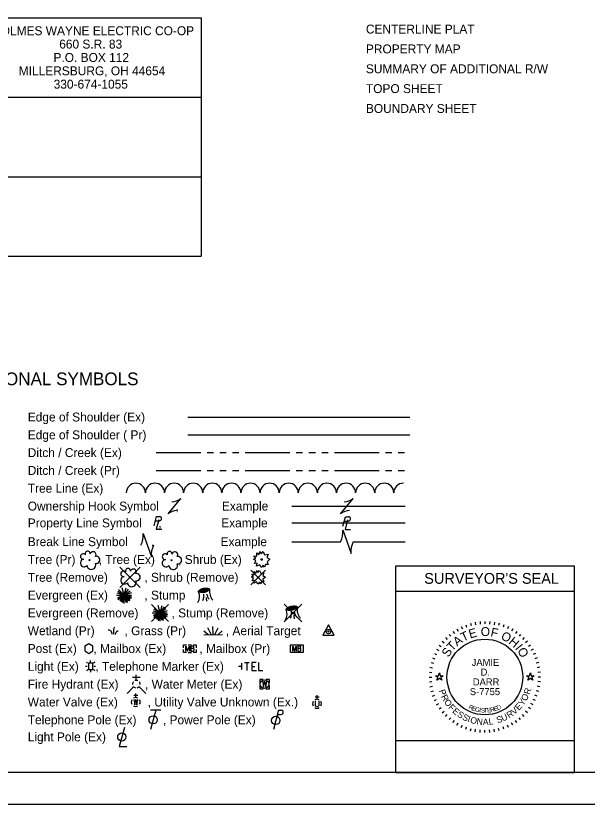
# Model space of a CAD drawing. Extents: x 0 to 34, y 0 to 22.
# Drawn here: x 8.19 to 17.17, y 0 to 12.39 of the extents above; entities that cross this region are included whole.
import ezdxf

# ---------------------------------------------------------------- set-up
doc = ezdxf.new("R2010")
doc.units = 0
for name, color, linetype in [('Default', 7, 'Continuous'), ('SH_Border', 7, 'Continuous'), ('SH_Cut_Line', 7, 'Continuous'), ('SH_Data', 7, 'Continuous'), ('SH_Seal', 7, 'Continuous'), ('SH_Text', 7, 'Continuous')]:
    doc.layers.add(name, color=color, linetype=linetype)

msp = doc.modelspace()

# ---------------------------------------------------------------- linework, layer by layer
at = {"layer": 'Default'}
for p, q in [((6.8, 12.364), (11.105, 12.364)), ((11.105, 12.364), (11.105, 11.114)), ((6.8, 11.114), (11.105, 11.114)), ((6.8, 11.114), (11.105, 11.114)), ((11.105, 11.114), (11.105, 9.864)), ((6.8, 9.864), (11.105, 9.864)), ((6.8, 9.864), (11.105, 9.864)), ((11.105, 9.864), (11.105, 8.614)), ((6.8, 8.614), (11.105, 8.614))]:
    msp.add_line(p, q, dxfattribs=at)
at = {"layer": 'SH_Border'}
msp.add_lwpolyline([(1.5, 21.5), (33.5, 21.5), (33.5, 0.5), (1.5, 0.5)], close=True, dxfattribs=at)
at = {"layer": 'SH_Cut_Line'}
msp.add_lwpolyline([(0, 0), (34, 0), (34, 22), (0, 22)], close=True, dxfattribs=at)
at = {"layer": 'SH_Data'}
for p, q in [((14.16, 0.5), (14.16, 3.75)), ((14.16, 3.75), (16.96, 3.75)), ((16.96, 3.75), (16.96, 0.5)), ((14.16, 3.35), (16.96, 3.35)), ((14.16, 0.5), (16.96, 0.5))]:
    msp.add_line(p, q, dxfattribs=at)
msp.add_lwpolyline([(14.16, 0.5), (14.16, 1), (16.96, 1), (16.96, 0.5)], close=True, dxfattribs=at)
at = {"layer": 'SH_Seal'}
for p, q in [((15.408, 2.862), (15.415, 2.822)), ((15.484, 2.872), (15.487, 2.832)), ((15.56, 2.875), (15.56, 2.835)), ((15.636, 2.872), (15.633, 2.832)), ((15.712, 2.862), (15.705, 2.822)), ((15.122, 2.758), (15.142, 2.723)), ((15.19, 2.793), (15.207, 2.757)), ((15.261, 2.822), (15.274, 2.785)), ((15.333, 2.845), (15.344, 2.807)), ((15.786, 2.845), (15.776, 2.807)), ((15.859, 2.822), (15.845, 2.785)), ((15.93, 2.793), (15.913, 2.757)), ((15.997, 2.758), (15.977, 2.723)), ((14.941, 2.619), (14.969, 2.59)), ((14.997, 2.67), (15.023, 2.64)), ((15.058, 2.717), (15.081, 2.684)), ((16.062, 2.717), (16.039, 2.684)), ((16.122, 2.67), (16.097, 2.64)), ((16.179, 2.619), (16.15, 2.59)), ((14.843, 2.502), (14.876, 2.479)), ((14.89, 2.562), (14.92, 2.537)), ((16.23, 2.562), (16.199, 2.537)), ((16.277, 2.502), (16.244, 2.479)), ((14.767, 2.37), (14.803, 2.353)), ((14.802, 2.438), (14.837, 2.418)), ((16.318, 2.438), (16.283, 2.418)), ((16.353, 2.37), (16.317, 2.353)), ((14.738, 2.299), (14.775, 2.286)), ((16.382, 2.299), (16.344, 2.286)), ((14.698, 2.152), (14.737, 2.145)), ((14.715, 2.226), (14.753, 2.216)), ((16.405, 2.226), (16.366, 2.216)), ((16.422, 2.152), (16.382, 2.145)), ((14.685, 2), (14.725, 2)), ((14.688, 2.076), (14.728, 2.073)), ((16.431, 2.076), (16.392, 2.073)), ((16.435, 2), (16.395, 2)), ((14.688, 1.924), (14.728, 1.927)), ((16.431, 1.924), (16.392, 1.927)), ((14.698, 1.848), (14.737, 1.855)), ((14.715, 1.774), (14.753, 1.784)), ((16.405, 1.774), (16.366, 1.784)), ((16.422, 1.848), (16.382, 1.855)), ((14.738, 1.701), (14.775, 1.714)), ((14.767, 1.63), (14.803, 1.647)), ((16.353, 1.63), (16.317, 1.647)), ((16.382, 1.701), (16.344, 1.714)), ((14.802, 1.563), (14.837, 1.583)), ((14.843, 1.498), (14.876, 1.521)), ((16.277, 1.498), (16.244, 1.521)), ((16.318, 1.563), (16.283, 1.583)), ((14.89, 1.438), (14.92, 1.463)), ((14.941, 1.381), (14.969, 1.41)), ((16.179, 1.381), (16.15, 1.41)), ((16.23, 1.438), (16.199, 1.463)), ((14.997, 1.33), (15.023, 1.36)), ((15.058, 1.283), (15.081, 1.316)), ((15.122, 1.242), (15.142, 1.277)), ((15.19, 1.207), (15.207, 1.243)), ((15.93, 1.207), (15.913, 1.243)), ((15.997, 1.242), (15.977, 1.277)), ((16.062, 1.283), (16.039, 1.316)), ((16.122, 1.33), (16.097, 1.36)), ((15.261, 1.178), (15.274, 1.215)), ((15.333, 1.155), (15.344, 1.193)), ((15.408, 1.138), (15.415, 1.178)), ((15.484, 1.128), (15.487, 1.168)), ((15.56, 1.125), (15.56, 1.165)), ((15.636, 1.128), (15.633, 1.168)), ((15.712, 1.138), (15.705, 1.178)), ((15.786, 1.155), (15.776, 1.193)), ((15.859, 1.178), (15.845, 1.215))]:
    msp.add_line(p, q, dxfattribs=at)
for points in [[(14.783, 2.02), (14.83, 2.02), (14.845, 2.065), (14.859, 2.02), (14.906, 2.02), (14.868, 1.992), (14.883, 1.948), (14.845, 1.975), (14.807, 1.948), (14.821, 1.992)], [(16.213, 2.02), (16.26, 2.02), (16.275, 2.065), (16.289, 2.02), (16.336, 2.02), (16.298, 1.992), (16.313, 1.948), (16.275, 1.975), (16.237, 1.948), (16.251, 1.992)]]:
    msp.add_lwpolyline(points, close=True, dxfattribs=at)
msp.add_circle((15.56, 2), 0.595, dxfattribs=at)
at = {"layer": 'SH_Text'}
for p, q in [((10.898, 6.087), (14.382, 6.087)), ((10.898, 5.807), (14.382, 5.807)), ((10.398, 5.527), (11.098, 5.527)), ((11.198, 5.527), (11.298, 5.527)), ((11.398, 5.527), (11.498, 5.527)), ((11.598, 5.527), (11.698, 5.527)), ((11.798, 5.527), (12.498, 5.527)), ((12.598, 5.527), (12.698, 5.527)), ((12.798, 5.527), (12.898, 5.527)), ((12.998, 5.527), (13.098, 5.527)), ((13.198, 5.527), (13.898, 5.527)), ((13.998, 5.527), (14.098, 5.527)), ((14.198, 5.527), (14.298, 5.527)), ((10.398, 5.247), (11.098, 5.247)), ((11.198, 5.247), (11.298, 5.247)), ((11.398, 5.247), (11.498, 5.247)), ((11.598, 5.247), (11.698, 5.247)), ((11.798, 5.247), (12.498, 5.247)), ((12.598, 5.247), (12.698, 5.247)), ((12.798, 5.247), (12.898, 5.247)), ((12.998, 5.247), (13.098, 5.247)), ((13.198, 5.247), (13.898, 5.247)), ((13.998, 5.247), (14.098, 5.247)), ((14.198, 5.247), (14.298, 5.247)), ((10.585, 4.567), (10.785, 4.807)), ((13.294, 4.567), (13.494, 4.807)), ((10.685, 4.687), (10.685, 4.687)), ((12.528, 4.687), (14.31, 4.687)), ((13.394, 4.687), (13.394, 4.687)), ((10.386, 4.456), (10.45, 4.456)), ((10.426, 4.424), (10.426, 4.424)), ((12.528, 4.422), (14.31, 4.422)), ((13.351, 4.451), (13.416, 4.451)), ((13.391, 4.42), (13.391, 4.42)), ((10.193, 4.255), (10.323, 3.887)), ((13.329, 4.311), (13.459, 3.942)), ((12.528, 4.127), (13.294, 4.127)), ((13.394, 4.127), (13.394, 4.127)), ((13.493, 4.127), (14.31, 4.127)), ((10.258, 4.071), (10.258, 4.071)), ((9.826, 3.727), (10.146, 3.406)), ((10.146, 3.727), (9.826, 3.406)), ((11.885, 3.682), (12.117, 3.451)), ((12.117, 3.682), (11.885, 3.451)), ((9.986, 3.567), (9.986, 3.567)), ((12.001, 3.567), (12.001, 3.567)), ((9.897, 3.286), (9.809, 3.373)), ((9.897, 3.286), (9.866, 3.402)), ((9.897, 3.286), (9.928, 3.404)), ((9.897, 3.286), (9.963, 3.383)), ((9.897, 3.286), (9.988, 3.356)), ((9.773, 3.286), (9.897, 3.286)), ((9.897, 3.286), (9.786, 3.316)), ((9.897, 3.286), (9.789, 3.247)), ((9.897, 3.286), (9.797, 3.229)), ((9.897, 3.286), (9.799, 3.344)), ((9.897, 3.286), (9.799, 3.211)), ((9.897, 3.286), (9.823, 3.2)), ((9.897, 3.286), (9.839, 3.186)), ((9.897, 3.286), (9.855, 3.178)), ((9.897, 3.286), (9.865, 3.165)), ((9.897, 3.286), (9.883, 3.172)), ((9.897, 3.286), (10.015, 3.326)), ((9.897, 3.286), (10.009, 3.289)), ((9.897, 3.155), (9.897, 3.286)), ((9.897, 3.286), (9.92, 3.17)), ((9.897, 3.286), (9.945, 3.17)), ((9.897, 3.286), (9.96, 3.191)), ((9.897, 3.286), (9.986, 3.198)), ((9.897, 3.286), (9.992, 3.222)), ((9.897, 3.286), (10.008, 3.238)), ((9.897, 3.286), (10.017, 3.262)), ((11.17, 3.287), (11.17, 3.287)), ((10.327, 3.14), (10.594, 2.873)), ((10.594, 3.14), (10.327, 2.873)), ((10.461, 3.007), (10.43, 3.122)), ((10.461, 3.007), (10.492, 3.124)), ((10.461, 3.007), (10.527, 3.104)), ((12.407, 3.146), (12.685, 2.867)), ((12.685, 3.146), (12.407, 2.867)), ((10.337, 3.007), (10.461, 3.007)), ((10.461, 3.007), (10.35, 3.036)), ((10.461, 3.007), (10.353, 2.967)), ((10.461, 3.007), (10.361, 2.949)), ((10.461, 3.007), (10.363, 3.064)), ((10.461, 3.007), (10.363, 2.932)), ((10.461, 3.007), (10.373, 3.094)), ((10.461, 3.007), (10.387, 2.92)), ((10.461, 3.007), (10.403, 2.906)), ((10.461, 3.007), (10.419, 2.898)), ((10.461, 3.007), (10.429, 2.885)), ((10.461, 3.007), (10.447, 2.892)), ((10.461, 3.007), (10.552, 3.077)), ((10.461, 3.007), (10.579, 3.047)), ((10.461, 3.007), (10.573, 3.009)), ((10.461, 2.876), (10.461, 3.007)), ((10.461, 3.007), (10.484, 2.891)), ((10.461, 3.007), (10.509, 2.89)), ((10.461, 3.007), (10.524, 2.912)), ((10.461, 3.007), (10.55, 2.918)), ((10.461, 3.007), (10.556, 2.943)), ((10.461, 3.007), (10.572, 2.958)), ((10.461, 3.007), (10.581, 2.983)), ((10.461, 3.007), (10.461, 3.007)), ((12.546, 3.007), (12.546, 3.007)), ((12.546, 3.007), (12.546, 3.007)), ((11.262, 2.666), (11.21, 2.772)), ((11.292, 2.667), (11.29, 2.792)), ((11.322, 2.667), (11.371, 2.775)), ((11.371, 2.668), (11.437, 2.727)), ((11.214, 2.665), (11.145, 2.722)), ((11.146, 2.664), (11.438, 2.669)), ((10.903, 2.508), (10.953, 2.508)), ((10.903, 2.385), (10.953, 2.385)), ((10.929, 2.447), (10.929, 2.447)), ((12.607, 2.447), (12.607, 2.447)), ((9.321, 2.215), (9.303, 2.234)), ((9.369, 2.231), (9.369, 2.257)), ((9.436, 2.234), (9.417, 2.215)), ((9.317, 2.167), (9.291, 2.167)), ((9.321, 2.118), (9.303, 2.099)), ((9.369, 2.167), (9.369, 2.167)), ((9.436, 2.099), (9.417, 2.118)), ((9.448, 2.167), (9.421, 2.167)), ((11.742, 2.167), (11.692, 2.167)), ((11.742, 2.117), (11.742, 2.217)), ((9.369, 2.103), (9.369, 2.076)), ((10.147, 1.99), (10.027, 1.99)), ((10.087, 1.947), (10.087, 2.033)), ((10.087, 1.887), (10.087, 1.887)), ((10.087, 1.887), (10.087, 1.887)), ((12.101, 1.887), (12.101, 1.887)), ((10.045, 1.844), (9.941, 1.74)), ((10.078, 1.677), (10.078, 1.74)), ((10.13, 1.844), (10.234, 1.74)), ((10.11, 1.708), (10.046, 1.708)), ((12.956, 1.682), (12.893, 1.682)), ((12.897, 1.623), (12.897, 1.554)), ((12.924, 1.65), (12.924, 1.714)), ((12.952, 1.623), (12.952, 1.554)), ((10.078, 1.607), (10.078, 1.607)), ((12.924, 1.58), (12.924, 1.58)), ((10.471, 1.477), (10.311, 1.477)), ((10.391, 1.477), (10.311, 1.177)), ((12.32, 1.477), (12.24, 1.177)), ((12.303, 1.413), (12.363, 1.413)), ((12.32, 1.477), (12.363, 1.477))]:
    msp.add_line(p, q, dxfattribs=at)
for points in [[(10.365, 4.376), (10.404, 4.524), (10.455, 4.524)], [(10.439, 4.472), (10.399, 4.325), (10.487, 4.325)], [(13.33, 4.372), (13.369, 4.52), (13.421, 4.52)], [(13.405, 4.468), (13.365, 4.32), (13.452, 4.32)], [(12.049, 3.937), (12.08, 3.974), (12.1, 3.921), (12.155, 3.93), (12.138, 3.88), (12.185, 3.85), (12.143, 3.813), (12.155, 3.767), (12.117, 3.771), (12.101, 3.725), (12.08, 3.76), (12.046, 3.719), (12.024, 3.763), (11.973, 3.742), (11.983, 3.789), (11.942, 3.785), (11.966, 3.824), (11.928, 3.853), (11.965, 3.866), (11.934, 3.906), (11.981, 3.9), (11.979, 3.952), (12.017, 3.924), (12.027, 3.973), (12.049, 3.937)], [(11.997, 3.643), (12.023, 3.675), (12.04, 3.63), (12.087, 3.638), (12.072, 3.595), (12.113, 3.569), (12.076, 3.538), (12.087, 3.499), (12.055, 3.502), (12.041, 3.463), (12.023, 3.493), (11.994, 3.458), (11.976, 3.496), (11.932, 3.477), (11.941, 3.517), (11.906, 3.514), (11.926, 3.547), (11.894, 3.572), (11.925, 3.583), (11.899, 3.617), (11.939, 3.612), (11.937, 3.656), (11.969, 3.632), (11.978, 3.674), (11.997, 3.643)], [(9.276, 2.409), (9.341, 2.372), (9.406, 2.409), (9.406, 2.484), (9.341, 2.522), (9.276, 2.484), (9.276, 2.409)], [(10.829, 2.459), (10.829, 2.508), (10.877, 2.508)], [(10.864, 2.407), (10.864, 2.487), (10.893, 2.407), (10.921, 2.487), (10.921, 2.407)], [(10.98, 2.45), (10.983, 2.453), (10.985, 2.455), (10.986, 2.457), (10.987, 2.458), (10.988, 2.461), (10.989, 2.463), (10.99, 2.467), (10.99, 2.469), (10.99, 2.471), (10.989, 2.475), (10.988, 2.478), (10.986, 2.481), (10.983, 2.483), (10.981, 2.485), (10.979, 2.485), (10.976, 2.487), (10.945, 2.487), (10.945, 2.407), (10.98, 2.407), (10.984, 2.409), (10.988, 2.412), (10.991, 2.417), (10.993, 2.423), (10.994, 2.429), (10.994, 2.432), (10.993, 2.436), (10.99, 2.442), (10.987, 2.446), (10.98, 2.45), (10.945, 2.45)], [(10.979, 2.508), (11.029, 2.508), (11.029, 2.459)], [(12.542, 2.407), (12.542, 2.487), (12.571, 2.407), (12.599, 2.487), (12.599, 2.407)], [(12.658, 2.45), (12.661, 2.453), (12.663, 2.455), (12.664, 2.457), (12.665, 2.458), (12.666, 2.461), (12.667, 2.463), (12.668, 2.467), (12.668, 2.469), (12.668, 2.471), (12.668, 2.475), (12.666, 2.478), (12.664, 2.481), (12.661, 2.483), (12.659, 2.485), (12.658, 2.485), (12.654, 2.487), (12.624, 2.487), (12.624, 2.407), (12.658, 2.407), (12.663, 2.409), (12.666, 2.412), (12.67, 2.417), (12.671, 2.423), (12.672, 2.429), (12.672, 2.432), (12.671, 2.436), (12.668, 2.442), (12.665, 2.446), (12.658, 2.45), (12.624, 2.45)], [(10.877, 2.385), (10.829, 2.385), (10.829, 2.434)], [(11.029, 2.434), (11.029, 2.385), (10.979, 2.385)], [(11.783, 2.229), (11.861, 2.229)], [(11.822, 2.229), (11.822, 2.104)], [(11.968, 2.229), (11.9, 2.229), (11.9, 2.104), (11.973, 2.104)], [(11.9, 2.167), (11.948, 2.167)], [(12.007, 2.229), (12.007, 2.104), (12.075, 2.104)], [(12.081, 1.962), (12.026, 1.962), (12.026, 1.907)], [(12.026, 1.867), (12.026, 1.812), (12.081, 1.812)], [(12.068, 1.932), (12.084, 1.842), (12.101, 1.932), (12.118, 1.842), (12.134, 1.932)], [(12.176, 1.907), (12.176, 1.962), (12.121, 1.962)], [(12.121, 1.812), (12.176, 1.812), (12.176, 1.867)], [(10.046, 1.648), (10.062, 1.561), (10.078, 1.648), (10.094, 1.561), (10.11, 1.648)], [(9.899, 1.205), (9.82, 0.906), (9.938, 0.906)]]:
    msp.add_lwpolyline(points, dxfattribs=at)
for points in [[(13.015, 2.657), (13.195, 2.657), (13.105, 2.818)], [(12.507, 2.508), (12.707, 2.508), (12.707, 2.385), (12.507, 2.385)], [(9.336, 2.117), (9.403, 2.117), (9.403, 2.217), (9.336, 2.217)]]:
    msp.add_lwpolyline(points, close=True, dxfattribs=at)
for centre, radius in [((9.353, 3.838), 0.0084), ((12.054, 3.847), 0.0115), ((10.638, 3.835), 0.0072), ((9.986, 3.567), 0.0072), ((12.001, 3.567), 0.00979), ((13.105, 2.714), 0.035), ((13.105, 2.714), 0.008), ((12.101, 1.887), 0.0675), ((10.351, 1.327), 0.065), ((12.277, 1.317), 0.065), ((9.859, 1.058), 0.065)]:
    msp.add_circle(centre, radius, dxfattribs=at)
for centre, radius, start, end in [((10.08, 4.896), 0.15, 0.0098, 179.9926), ((10.38, 4.896), 0.15, 0.0098, 179.9926), ((10.68, 4.896), 0.15, 0.0098, 179.9926), ((10.98, 4.896), 0.15, 0.0098, 179.9926), ((11.28, 4.896), 0.15, 0.0098, 179.9926), ((11.58, 4.896), 0.15, 0.0098, 179.9926), ((11.88, 4.896), 0.15, 0.0098, 179.9926), ((12.18, 4.896), 0.15, 0.0098, 179.9926), ((12.48, 4.896), 0.15, 0.0098, 179.9926), ((12.78, 4.896), 0.15, 0.0098, 179.9926), ((13.08, 4.896), 0.15, 0.0098, 179.9926), ((13.38, 4.896), 0.15, 0.0098, 179.9926), ((13.68, 4.896), 0.15, 0.0098, 179.9926), ((13.98, 4.896), 0.15, 0.0098, 179.9926), ((14.28, 4.896), 0.15, 89.9955, 179.9926), ((10.627, 5.021), 0.267, 273.6945, 306.337), ((13.335, 5.021), 0.267, 273.6945, 306.337), ((10.743, 4.352), 0.267, 93.6945, 126.337), ((13.452, 4.352), 0.267, 93.6945, 126.337), ((10.45, 4.49), 0.0345, 270.471, 81.3281), ((13.416, 4.486), 0.0345, 270.471, 81.3281), ((9.861, 4.223), 0.334, 332.9422, 5.5848), ((12.997, 4.278), 0.334, 332.9422, 5.5848), ((13.79, 3.975), 0.334, 152.9422, 185.5848), ((9.324, 3.939), 0.0395, 354.0047, 205.9741), ((9.408, 3.923), 0.0466, 323.83, 165.0376), ((10.655, 3.919), 0.334, 152.9422, 185.5848), ((10.608, 3.936), 0.0395, 354.0047, 205.9741), ((10.692, 3.92), 0.0466, 323.83, 165.0376), ((9.267, 3.792), 0.0592, 96.1722, 320.5737), ((9.254, 3.894), 0.0441, 39.0625, 279.5412), ((9.457, 3.84), 0.0574, 259.1453, 101.4596), ((10.552, 3.789), 0.0592, 96.1722, 320.5737), ((10.538, 3.891), 0.0441, 39.0625, 279.5412), ((10.741, 3.836), 0.0574, 259.1453, 101.4596), ((9.381, 3.76), 0.0685, 184.9476, 19.4572), ((10.666, 3.757), 0.0685, 184.9476, 19.4572), ((9.887, 3.622), 0.0441, 39.0625, 279.5412), ((9.957, 3.668), 0.0395, 354.0047, 205.9741), ((10.041, 3.651), 0.0466, 323.83, 165.0376), ((10.09, 3.568), 0.0574, 259.1453, 101.4596), ((9.9, 3.52), 0.0592, 96.1722, 320.5737), ((10.014, 3.488), 0.0685, 184.9476, 19.4572), ((11.451, 3.344), 0.215, 171.4106, 219.9194), ((10.879, 3.269), 0.2, 331.5338, 20.9269), ((10.894, 3.288), 0.253, 340.7938, 3.5481), ((11.366, 3.247), 0.182, 178.7926, 197.1224), ((11.496, 3.389), 0.316, 194.9653, 212.1216), ((12.254, 2.989), 0.2, 331.5338, 20.9269), ((12.27, 3.008), 0.253, 340.7938, 3.5481), ((12.871, 3.109), 0.316, 194.9653, 212.1216), ((12.826, 3.064), 0.215, 171.4106, 219.9194), ((12.741, 2.967), 0.182, 178.7926, 197.1224), ((10.087, 1.887), 0.06, 140.021, 184.0629), ((10.087, 1.887), 0.06, 68.1395, 112.038), ((10.087, 1.887), 0.06, 356.0165, 39.9889), ((10.087, 1.887), 0.06, 211.8788, 255.8479), ((10.087, 1.887), 0.06, 283.8239, 329.9097), ((10.078, 1.607), 0.07, 150.0184, 209.9816), ((10.078, 1.607), 0.07, 60.0184, 120.0157), ((10.078, 1.607), 0.07, 330.0184, 29.9816), ((12.924, 1.58), 0.07, 150.0184, 209.9816), ((12.924, 1.58), 0.07, 60.0184, 120.0157), ((12.924, 1.58), 0.07, 330.0184, 29.9816), ((10.078, 1.607), 0.07, 239.9843, 299.9816), ((12.924, 1.58), 0.07, 239.9843, 299.9816), ((12.924, 1.567), 0.03, 205.1924, 334.8076), ((12.363, 1.445), 0.0319, 268.8767, 91.1233)]:
    msp.add_arc(centre, radius, start, end, dxfattribs=at)
for centre, major_axis in [((11.151, 3.362), (0.0868, 0.0187)), ((11.151, 3.362), (0.0651, 0.0141)), ((11.151, 3.362), (0.0488, 0.0105)), ((11.151, 3.362), (0.0275, 0.0059)), ((11.151, 3.362), (0.0154, 0.0033)), ((12.527, 3.082), (0.0868, 0.0187)), ((12.527, 3.082), (0.0651, 0.0141)), ((12.527, 3.082), (0.0488, 0.0105)), ((12.527, 3.082), (0.0275, 0.0059)), ((12.527, 3.082), (0.0154, 0.0033))]:
    msp.add_ellipse(centre, major_axis=major_axis, ratio=0.36865, dxfattribs=at)
for points in [[(9.645, 2.742), (9.687, 2.724), (9.704, 2.671)], [(9.733, 2.675), (9.733, 2.722), (9.739, 2.767), (9.747, 2.788)], [(9.76, 2.668), (9.772, 2.706), (9.802, 2.73)]]:
    msp.add_spline(points, degree=3, dxfattribs=at)

# ---------------------------------------------------------------- texts
at = {"layer": 'Default'}
for s, p in [('HOLMES WAYNE ELECTRIC CO-OP', (7.822, 12.089)), ('660 S.R. 83', (8.876, 11.879)), ('P.O. BOX 112', (8.786, 11.669)), ('MILLERSBURG, OH 44654', (8.241, 11.459)), ('330-674-1055', (8.789, 11.249))]:
    msp.add_text(s, height=0.14, dxfattribs=at).set_placement(p)
at = {"layer": 'SH_Data'}
for s, height, p in [('CENTERLINE PLAT                    ', 0.14, (13.692, 12.115)), ('PROPERTY MAP                       ', 0.14, (13.692, 11.803)), ('SUMMARY OF ADDITIONAL R/W          ', 0.14, (13.692, 11.491)), ('TOPO SHEET                         ', 0.14, (13.692, 11.179)), ('BOUNDARY SHEET                     ', 0.14, (13.692, 10.867)), ("SURVEYOR'S SEAL", 0.17, (14.608, 3.465))]:
    msp.add_text(s, height=height, dxfattribs=at).set_placement(p)
at = {"layer": 'SH_Seal'}
for s, height, rotation, p in [('E', 0.14, 15.7571, (15.328, 2.604)), ('O', 0.14, 359.7812, (15.495, 2.644)), ('F', 0.14, 347.4362, (15.641, 2.642)), ('A', 0.14, 36.4747, (15.123, 2.478)), ('T', 0.14, 25.7167, (15.221, 2.552)), ('O', 0.14, 332.2586, (15.8, 2.602)), ('H', 0.14, 319.9136, (15.923, 2.536)), ('T', 0.14, 46.4344, (15.048, 2.396)), ('I', 0.14, 308.367, (16.026, 2.448)), ('S', 0.14, 57.1924, (14.988, 2.301)), ('O', 0.14, 303.1491, (16.062, 2.409)), ('P', 0.1, 289.7431, (14.835, 1.784)), ('R', 0.1, 70.983, (16.261, 1.717)), ('R', 0.1, 296.9802, (14.869, 1.693)), ('O', 0.1, 304.7158, (14.913, 1.608)), ('Y', 0.1, 55.5058, (16.16, 1.54)), ('O', 0.1, 62.7428, (16.21, 1.613)), ('F', 0.1, 312.956, (14.979, 1.516)), ('E', 0.1, 319.6885, (15.041, 1.45)), ('R', 0.07, 334.487, (15.297, 1.505)), ('E', 0.07, 341.04, (15.35, 1.48)), ('G', 0.07, 347.4752, (15.401, 1.462)), ('I', 0.07, 353.7858, (15.469, 1.447)), ('S', 0.07, 356.8926, (15.496, 1.443)), ('T', 0.07, 3.0061, (15.545, 1.439)), ('E', 0.07, 6.0117, (15.599, 1.441)), ('R', 0.07, 11.9184, (15.652, 1.447)), ('E', 0.07, 17.6836, (15.71, 1.46)), ('D', 0.07, 23.3052, (15.761, 1.477)), ('V', 0.1, 41.0316, (16.021, 1.401)), ('E', 0.1, 48.2687, (16.096, 1.467)), ('S', 0.1, 326.9255, (15.115, 1.389)), ('S', 0.1, 334.1626, (15.196, 1.337)), ('I', 0.1, 341.3997, (15.279, 1.298)), ('O', 0.1, 345.1351, (15.322, 1.282)), ('S', 0.1, 18.3234, (15.76, 1.271)), ('U', 0.1, 25.5604, (15.843, 1.299)), ('R', 0.1, 33.296, (15.941, 1.347)), ('N', 0.1, 353.3752, (15.426, 1.255)), ('A', 0.1, 1.1108, (15.529, 1.244)), ('L', 0.1, 8.3479, (15.626, 1.247))]:
    msp.add_text(s, height=height, rotation=rotation, dxfattribs=at).set_placement(p)
for s, p in [('JAMIE', (15.353, 2.175)), ('D.', (15.493, 2.022)), ('DARR', (15.371, 1.868)), ('S-7755', (15.324, 1.715))]:
    msp.add_text(s, height=0.11, dxfattribs=at).set_placement(p)
at = {"layer": 'SH_Text'}
for s, height, p in [('CONVENTIONAL SYMBOLS', 0.2, (6.643, 6.587)), ('Edge of Shoulder (Ex)', 0.14, (8.382, 6.017)), ('Edge of Shoulder ( Pr)', 0.14, (8.382, 5.737)), ('Ditch / Creek (Ex)', 0.14, (8.382, 5.457)), ('Ditch / Creek (Pr)', 0.14, (8.382, 5.177)), ('Tree Line (Ex)', 0.14, (8.382, 4.897)), ('Ownership Hook Symbol     ,             Example', 0.14, (8.382, 4.617)), ('Property Line Symbol     ,                  Example', 0.14, (8.382, 4.352)), ('Break Line Symbol       ,                    Example', 0.14, (8.382, 4.057)), ('Tree (Pr)       , Tree (Ex)       , Shrub (Ex)', 0.14, (8.382, 3.777)), ('Tree (Remove)           , Shrub (Remove)', 0.14, (8.382, 3.497)), ('Evergreen (Ex)           , Stump ', 0.14, (8.382, 3.217)), ('Evergreen (Remove)          , Stump (Remove)', 0.14, (8.382, 2.937)), ('Wetland (Pr)         , Grass (Pr)            , Aerial Target    ', 0.14, (8.382, 2.657)), ('Post (Ex)     , Mailbox (Ex)          , Mailbox (Pr)', 0.14, (8.382, 2.377)), ('Light (Ex)     , Telephone Marker (Ex)     ', 0.14, (8.382, 2.097)), ('Fire Hydrant (Ex)        , Water Meter (Ex)', 0.14, (8.382, 1.817)), ('Water Valve (Ex)         , Utility Valve Unknown (Ex.)', 0.14, (8.382, 1.537)), ('Telephone Pole (Ex)        , Power Pole (Ex)', 0.14, (8.382, 1.257)), ('Light Pole (Ex)     ', 0.14, (8.382, 0.989))]:
    msp.add_text(s, height=height, dxfattribs=at).set_placement(p)

doc.saveas('drawing.dxf')
